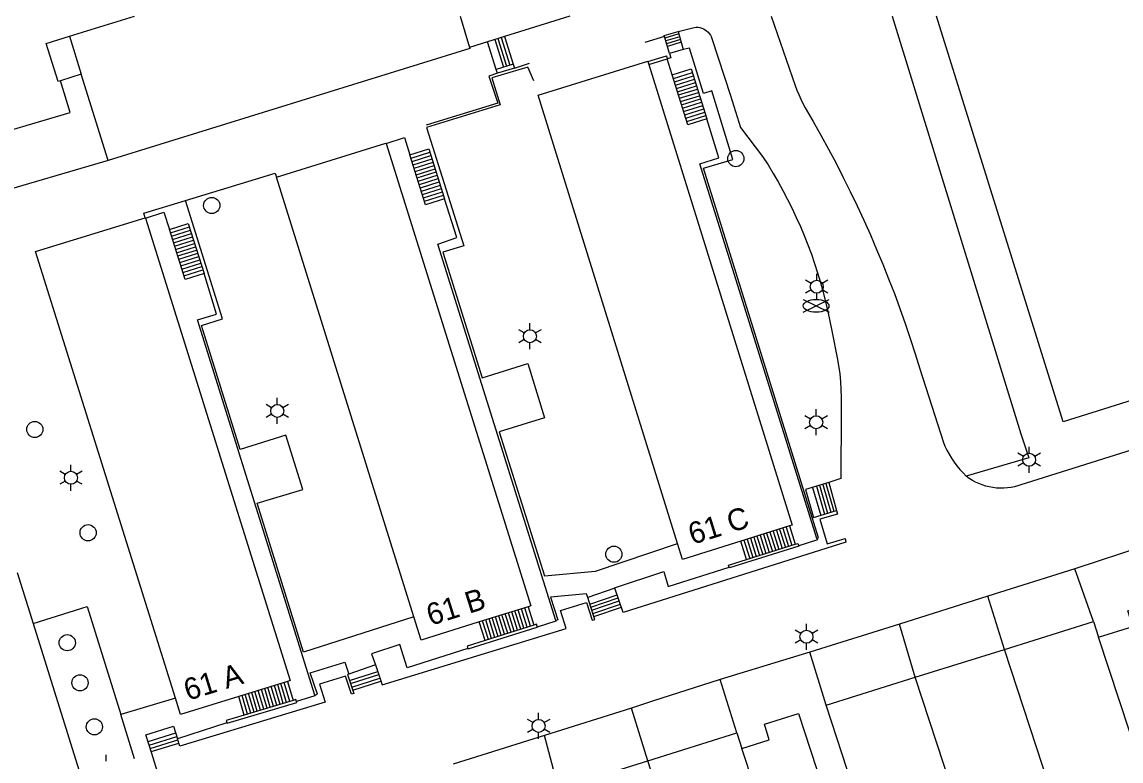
# Model space of a CAD drawing. Extents: x 122462 to 123306, y 485548 to 486417.
# Drawn here: x 122701.5 to 122777.6, y 486198.4 to 486249.6 of the extents above; entities that cross this region are included whole.
import ezdxf

# ---------------------------------------------------------------- set-up
doc = ezdxf.new("R2010")
doc.units = 0
for name, color, linetype in [('B-WE-IE-MEUBILAIR_WEGMEUBILAIR_VERKEERSBORD-S', 7, 'Continuous'), ('Level 1', 7, 'Continuous'), ('Level 17', 7, 'Continuous'), ('Level 19', 7, 'Continuous'), ('Level 21', 7, 'Continuous'), ('Level 31', 7, 'Continuous'), ('Level 33', 7, 'Continuous'), ('Level 4', 7, 'Continuous'), ('Level 50', 7, 'Continuous'), ('Level 52', 7, 'Continuous'), ('Level 53', 7, 'Continuous'), ('N-WE-AL-T25', 7, 'Continuous')]:
    doc.layers.add(name, color=color, linetype=linetype)

msp = doc.modelspace()

# ---------------------------------------------------------------- linework, layer by layer
at = {"layer": 'Level 1'}
for p, q in [((122704.806, 486248.607), (122709.3, 486250)), ((122739.426, 486250), (122734.916, 486248.585)), ((122734.916, 486248.585), (122733.743, 486248.217)), ((122733.743, 486248.217), (122732.497, 486247.826)), ((122744.836, 486246.849), (122744.901, 486246.641)), ((122728.649, 486208.4), (122719.125, 486238.839)), ((122710.053, 486236.037), (122710.064, 486236.01)), ((122754.637, 486214.699), (122751.263, 486213.648)), ((122780.735, 486213.823), (122774.385, 486211.733)), ((122701.191, 486211.491), (122702.294, 486207.955)), ((122774.385, 486211.733), (122768.357, 486209.846)), ((122768.357, 486209.846), (122762.257, 486207.893)), ((122736.54, 486209.108), (122733.171, 486208.054)), ((122769.508, 486206.159), (122775.679, 486208.086)), ((122775.679, 486208.086), (122776.018, 486207)), ((122702.294, 486207.955), (122706.11, 486195.719)), ((122762.257, 486207.893), (122756.038, 486205.965)), ((122756.038, 486205.965), (122749.842, 486204.065)), ((122763.336, 486204.232), (122769.508, 486206.159)), ((122757.165, 486202.305), (122763.336, 486204.232)), ((122719.89, 486203.937), (122716.522, 486202.896)), ((122743.708, 486202.097), (122737.689, 486200.198)), ((122760.501, 486192.189), (122757.165, 486202.305)), ((122737.689, 486200.198), (122731.364, 486198.223)), ((122744.822, 486198.451), (122750.993, 486200.378)), ((122750.993, 486200.378), (122751.331, 486199.294)), ((122738.65, 486196.524), (122744.822, 486198.451))]:
    msp.add_line(p, q, dxfattribs=at)
for points in [[(122780.782, 486224.161), (122773.57, 486221.91), (122764.823, 486250)], [(122704.175, 486245.515), (122704.015, 486245.466), (122703.196, 486248.108), (122704.806, 486248.607)], [(122732.497, 486247.826), (122732.509, 486247.762), (122721.776, 486244.438), (122707.472, 486240.007)], [(122746.894, 486213.482), (122737.25, 486244.529), (122744.826, 486246.877), (122744.836, 486246.849)], [(122744.901, 486246.641), (122754.828, 486214.758), (122754.637, 486214.699)], [(122698.105, 486241.345), (122704.857, 486243.315), (122704.175, 486245.515)], [(122719.125, 486238.839), (122722.916, 486240.025), (122726.706, 486241.211), (122726.715, 486241.182)], [(122726.715, 486241.182), (122736.73, 486209.167), (122736.54, 486209.108)], [(122707.472, 486240.007), (122699.259, 486237.61), (122699.226, 486237.726)], [(122712.133, 486202.784), (122702.462, 486233.692), (122710.053, 486236.037)], [(122710.064, 486236.01), (122720.079, 486203.995), (122719.89, 486203.937)], [(122751.263, 486213.648), (122747.231, 486212.391), (122746.894, 486213.482)], [(122776.018, 486207), (122778.405, 486207.745), (122778.066, 486208.831), (122781.851, 486210.013)], [(122733.171, 486208.054), (122729.15, 486206.795), (122728.649, 486208.4)], [(122749.842, 486204.065), (122745.162, 486202.563), (122743.708, 486202.097)], [(122716.522, 486202.896), (122712.488, 486201.65), (122712.133, 486202.784)], [(122751.331, 486199.294), (122753.241, 486199.89), (122752.903, 486200.974), (122755.256, 486201.709), (122757.349, 486195.363), (122756.4, 486195.05), (122757.497, 486191.726), (122757.179, 486191.095), (122754.363, 486190.167)]]:
    msp.add_lwpolyline(points, dxfattribs=at)
at = {"layer": 'Level 17'}
for p, q in [((122745.986, 486248.586), (122744.621, 486248.168)), ((122744.901, 486246.641), (122746.181, 486247.04)), ((122746.526, 486245.927), (122746.181, 486247.04)), ((122734.428, 486246.034), (122734.348, 486246.288)), ((122735.601, 486246.402), (122734.428, 486246.034)), ((122735.521, 486246.657), (122735.601, 486246.402)), ((122735.601, 486246.402), (122736.644, 486246.729)), ((122742.549, 486210.39), (122740.675, 486209.741)), ((122725.982, 486205.088), (122724.136, 486204.451)), ((122712.133, 486202.784), (122708.351, 486201.643)), ((122709.305, 486198.576), (122708.351, 486201.643)), ((122715.707, 486201.077), (122712.285, 486199.973))]:
    msp.add_line(p, q, dxfattribs=at)
for points in [[(122753.367, 486250), (122755.04, 486245.19), (122755.155, 486244.874), (122755.282, 486244.562), (122755.418, 486244.255), (122755.565, 486243.952), (122755.722, 486243.655), (122756.275, 486242.705), (122756.815, 486241.747), (122757.343, 486240.782), (122757.857, 486239.81), (122758.359, 486238.832), (122758.847, 486237.847), (122759.323, 486236.855), (122759.785, 486235.858), (122760.234, 486234.854), (122760.669, 486233.844), (122761.091, 486232.829), (122761.499, 486231.808), (122761.894, 486230.782), (122762.275, 486229.75), (122762.643, 486228.714), (122762.996, 486227.673), (122763.336, 486226.627), (122763.662, 486225.577), (122765.294, 486220.475), (122765.383, 486220.235), (122765.527, 486219.945), (122765.683, 486219.662), (122765.853, 486219.386), (122766.034, 486219.118), (122766.228, 486218.859), (122766.433, 486218.608), (122766.65, 486218.368), (122766.877, 486218.137)], [(122761.733, 486250), (122761.733, 486249.999), (122770.655, 486221.09), (122771.193, 486219.422), (122766.877, 486218.137)], [(122746.93, 486248.939), (122748.045, 486249.217), (122748.175, 486249.227), (122748.306, 486249.222), (122748.435, 486249.202), (122748.561, 486249.167), (122748.682, 486249.118), (122748.797, 486249.055), (122748.904, 486248.98), (122749.001, 486248.892), (122749.088, 486248.795), (122749.163, 486248.687), (122749.225, 486248.572), (122749.273, 486248.451), (122750.559, 486244.51), (122751.258, 486242.285), (122752.78, 486240.277), (122753.151, 486239.697), (122753.509, 486239.11), (122753.855, 486238.515), (122754.188, 486237.913), (122754.508, 486237.303), (122754.815, 486236.687), (122755.109, 486236.065), (122755.39, 486235.437), (122755.657, 486234.802), (122755.91, 486234.163), (122756.15, 486233.517), (122756.376, 486232.867), (122756.587, 486232.213), (122756.785, 486231.554), (122756.969, 486230.89), (122757.139, 486230.223), (122757.294, 486229.553), (122757.435, 486228.879), (122757.562, 486228.203), (122757.949, 486226.217), (122758.113, 486225.229), (122758.159, 486224.691), (122758.191, 486224.153), (122758.21, 486223.614), (122758.215, 486223.074), (122758.207, 486222.535), (122758.201, 486217.978), (122757.36, 486217.7), (122755.754, 486217.236), (122756.309, 486215.281), (122757.899, 486215.772), (122757.969, 486215.528), (122756.737, 486215.18), (122757.251, 486213.463), (122758.493, 486213.824), (122758.548, 486213.591), (122743.137, 486208.722), (122742.549, 486210.39)], [(122756.538, 486213.842), (122756.652, 486213.878), (122748.696, 486239.466), (122750.725, 486240.06), (122749.252, 486244.811), (122748.676, 486244.632), (122747.711, 486247.78), (122747.29, 486247.69)], [(122746.328, 486247.4), (122746.417, 486247.114), (122746.181, 486247.04)], [(122736.951, 486245.512), (122736.523, 486246.468), (122734.037, 486245.716), (122734.617, 486243.844), (122729.522, 486242.274), (122732.09, 486234.097), (122730.652, 486233.654), (122733.372, 486224.966), (122736.528, 486225.941), (122737.69, 486222.197), (122734.535, 486221.218), (122737.673, 486211.238), (122741.206, 486211.567), (122746.894, 486213.482)], [(122734.428, 486246.034), (122733.836, 486245.848), (122734.441, 486243.969), (122729.484, 486242.449)], [(122756.538, 486213.842), (122748.436, 486239.762), (122749.749, 486240.186), (122748.914, 486242.882)], [(122726.715, 486241.182), (122727.999, 486241.584), (122728.371, 486240.393)], [(122712.843, 486237.227), (122719.038, 486239.125), (122719.125, 486238.839)], [(122710.053, 486236.037), (122709.96, 486236.344), (122712.843, 486237.227)], [(122728.649, 486208.4), (122721, 486205.963), (122717.794, 486216.269), (122720.962, 486217.226), (122719.781, 486220.978), (122716.621, 486219.995), (122713.944, 486228.582), (122715.393, 486229.029), (122712.843, 486237.227)], [(122738.459, 486208.165), (122730.306, 486234.208), (122731.617, 486234.671), (122730.771, 486237.352)], [(122710.064, 486236.01), (122711.347, 486236.412), (122711.72, 486235.221)], [(122721.777, 486202.994), (122713.672, 486228.961), (122714.985, 486229.373), (122714.119, 486232.18)], [(122794.647, 486225.097), (122770.22, 486217.41), (122769.972, 486217.363), (122769.722, 486217.331), (122769.471, 486217.314), (122769.218, 486217.314), (122768.967, 486217.329), (122768.716, 486217.359), (122768.468, 486217.405), (122768.224, 486217.466), (122767.983, 486217.542), (122767.748, 486217.633), (122767.519, 486217.739), (122767.297, 486217.858), (122767.083, 486217.991), (122766.877, 486218.137)], [(122756.538, 486213.842), (122756.571, 486213.736), (122755.273, 486213.329)], [(122742.549, 486210.39), (122742.538, 486210.422), (122745.932, 486211.549), (122746.251, 486210.5), (122750.464, 486211.854)], [(122725.982, 486205.088), (122726.447, 486203.699), (122739.174, 486207.603), (122738.782, 486208.846), (122740.581, 486209.395), (122740.978, 486208.171), (122741.169, 486208.222), (122741.094, 486208.444), (122740.877, 486209.09), (122740.675, 486209.741)], [(122740.675, 486209.741), (122740.596, 486209.996), (122738.102, 486209.765), (122738.598, 486208.209), (122738.459, 486208.165)], [(122702.294, 486207.955), (122706.026, 486209.12), (122708.351, 486201.643)], [(122738.459, 486208.165), (122738.476, 486208.111), (122737.181, 486207.704)], [(122732.382, 486206.227), (122728.173, 486204.881), (122727.668, 486206.49), (122725.711, 486205.859), (122725.982, 486205.088)], [(122721.777, 486202.994), (122721.967, 486203.06), (122721.468, 486204.528), (122723.865, 486205.268), (122724.136, 486204.451)], [(122724.136, 486204.451), (122724.054, 486204.423), (122724.481, 486203.099), (122724.315, 486203.047), (122723.92, 486204.295), (122722.103, 486203.759), (122722.508, 486202.5), (122712.453, 486199.448), (122712.285, 486199.973)], [(122721.777, 486202.994), (122721.79, 486202.953), (122720.518, 486202.559)], [(122713.74, 486192.745), (122713.421, 486192.643), (122712.875, 486194.383), (122718.945, 486196.153), (122718.874, 486196.31), (122711.969, 486194.245), (122710.502, 486198.949), (122710.098, 486200.244), (122712.007, 486200.847), (122712.285, 486199.973)]]:
    msp.add_lwpolyline(points, dxfattribs=at)
at = {"layer": 'Level 19'}
for p, q in [((122778.917, 486198.257), (122776.018, 486207)), ((122772.778, 486196.235), (122769.508, 486206.159)), ((122766.64, 486194.212), (122763.336, 486204.232)), ((122754.363, 486190.167), (122751.331, 486199.294)), ((122748.225, 486188.145), (122744.822, 486198.451))]:
    msp.add_line(p, q, dxfattribs=at)
msp.add_lwpolyline([(122744.836, 486246.849), (122746.117, 486247.246), (122746.181, 486247.04)], dxfattribs=at)
at = {"layer": 'Level 21'}
for p, q in [((122751.663, 486212.375), (122755.032, 486213.431)), ((122736.937, 486207.837), (122733.571, 486206.78)), ((122720.281, 486202.621), (122716.903, 486201.613))]:
    msp.add_line(p, q, dxfattribs=at)
for points in [[(122755.032, 486213.431), (122755.222, 486213.491), (122755.24, 486213.435), (122755.273, 486213.329)], [(122755.273, 486213.329), (122755.282, 486213.3), (122750.483, 486211.795), (122750.464, 486211.854)], [(122750.464, 486211.854), (122750.423, 486211.986), (122751.663, 486212.375)], [(122732.382, 486206.227), (122732.391, 486206.2), (122737.181, 486207.704)], [(122737.181, 486207.704), (122737.164, 486207.758), (122737.121, 486207.895), (122736.937, 486207.837)], [(122733.571, 486206.78), (122732.331, 486206.391), (122732.382, 486206.227)], [(122715.707, 486201.077), (122715.715, 486201.049), (122720.539, 486202.489), (122720.518, 486202.559)], [(122720.518, 486202.559), (122720.482, 486202.681), (122720.281, 486202.621)], [(122716.903, 486201.613), (122715.658, 486201.241), (122715.707, 486201.077)]]:
    msp.add_lwpolyline(points, dxfattribs=at)
at = {"layer": 'Level 31'}
for p, q in [((122734.916, 486248.585), (122735.521, 486246.657)), ((122746.328, 486247.4), (122745.986, 486248.586)), ((122746.93, 486248.939), (122747.29, 486247.69)), ((122734.348, 486246.288), (122733.743, 486248.217)), ((122747.29, 486247.69), (122746.328, 486247.4)), ((122735.521, 486246.657), (122734.348, 486246.288)), ((122754.637, 486214.699), (122755.032, 486213.431)), ((122751.663, 486212.375), (122751.263, 486213.648)), ((122736.54, 486209.108), (122736.937, 486207.837)), ((122733.571, 486206.78), (122733.171, 486208.054)), ((122719.89, 486203.937), (122720.281, 486202.621)), ((122716.903, 486201.613), (122716.522, 486202.896))]:
    msp.add_line(p, q, dxfattribs=at)
for points in [[(122745.986, 486248.586), (122745.965, 486248.659), (122746.93, 486248.939)], [(122746.526, 486245.927), (122747.844, 486246.337), (122748.914, 486242.882)], [(122748.914, 486242.882), (122747.596, 486242.472), (122746.526, 486245.927)], [(122728.371, 486240.393), (122729.681, 486240.806), (122730.771, 486237.352)], [(122730.771, 486237.352), (122729.453, 486236.936), (122728.371, 486240.393)], [(122711.72, 486235.221), (122713.029, 486235.634), (122714.119, 486232.18)], [(122714.119, 486232.18), (122712.801, 486231.764), (122711.72, 486235.221)]]:
    msp.add_lwpolyline(points, dxfattribs=at)
at = {"layer": 'Level 33'}
for p, q in [((122734.236, 486248.371), (122734.838, 486246.453)), ((122734.457, 486248.441), (122735.057, 486246.53)), ((122734.688, 486248.513), (122735.288, 486246.601)), ((122746.983, 486248.757), (122746.02, 486248.467)), ((122747.038, 486248.565), (122746.076, 486248.275)), ((122747.094, 486248.372), (122746.131, 486248.082)), ((122747.149, 486248.18), (122746.187, 486247.89)), ((122746.602, 486245.682), (122747.915, 486246.09)), ((122746.673, 486245.452), (122747.986, 486245.861)), ((122746.744, 486245.223), (122748.058, 486245.632)), ((122746.815, 486244.994), (122748.133, 486245.404)), ((122746.886, 486244.764), (122748.204, 486245.175)), ((122746.957, 486244.535), (122748.275, 486244.945)), ((122747.028, 486244.306), (122748.346, 486244.716)), ((122747.099, 486244.077), (122748.417, 486244.487)), ((122747.17, 486243.848), (122748.488, 486244.258)), ((122747.241, 486243.618), (122748.559, 486244.029)), ((122747.312, 486243.388), (122748.63, 486243.799)), ((122747.383, 486243.159), (122748.701, 486243.57)), ((122747.454, 486242.93), (122748.772, 486243.34)), ((122747.525, 486242.701), (122748.843, 486243.111)), ((122728.443, 486240.164), (122729.753, 486240.577)), ((122728.515, 486239.935), (122729.825, 486240.348)), ((122728.586, 486239.705), (122729.898, 486240.119)), ((122728.658, 486239.476), (122729.97, 486239.891)), ((122728.73, 486239.247), (122730.042, 486239.662)), ((122728.801, 486239.018), (122730.114, 486239.433)), ((122728.877, 486238.791), (122730.187, 486239.204)), ((122728.949, 486238.562), (122730.259, 486238.975)), ((122729.021, 486238.333), (122730.331, 486238.746)), ((122729.094, 486238.104), (122730.403, 486238.517)), ((122729.166, 486237.875), (122730.476, 486238.288)), ((122729.238, 486237.646), (122730.548, 486238.06)), ((122729.31, 486237.417), (122730.62, 486237.831)), ((122729.382, 486237.188), (122730.692, 486237.602)), ((122711.791, 486234.992), (122713.102, 486235.405)), ((122711.863, 486234.763), (122713.174, 486235.176)), ((122711.935, 486234.534), (122713.246, 486234.947)), ((122712.006, 486234.304), (122713.318, 486234.718)), ((122712.078, 486234.075), (122713.391, 486234.49)), ((122712.15, 486233.846), (122713.463, 486234.261)), ((122712.221, 486233.617), (122713.535, 486234.032)), ((122712.298, 486233.39), (122713.607, 486233.803)), ((122712.37, 486233.161), (122713.679, 486233.574)), ((122712.442, 486232.932), (122713.752, 486233.345)), ((122712.514, 486232.703), (122713.824, 486233.116)), ((122712.586, 486232.474), (122713.896, 486232.887)), ((122712.659, 486232.245), (122713.968, 486232.659)), ((122712.731, 486232.016), (122714.041, 486232.43)), ((122756.234, 486217.375), (122756.796, 486215.431)), ((122756.501, 486217.452), (122757.061, 486215.513)), ((122756.719, 486217.515), (122757.278, 486215.58)), ((122756.938, 486217.578), (122757.495, 486215.647)), ((122757.157, 486217.641), (122757.713, 486215.715)), ((122757.36, 486217.7), (122757.899, 486215.772)), ((122752.833, 486214.137), (122753.232, 486212.867)), ((122753.057, 486214.207), (122753.456, 486212.937)), ((122753.283, 486214.277), (122753.681, 486213.008)), ((122753.507, 486214.347), (122753.905, 486213.078)), ((122753.731, 486214.416), (122754.129, 486213.148)), ((122753.955, 486214.486), (122754.353, 486213.219)), ((122754.179, 486214.556), (122754.577, 486213.289)), ((122754.404, 486214.626), (122754.802, 486213.359)), ((122751.487, 486213.718), (122751.887, 486212.445)), ((122751.711, 486213.788), (122752.111, 486212.515)), ((122751.935, 486213.857), (122752.335, 486212.586)), ((122752.16, 486213.928), (122752.56, 486212.656)), ((122752.385, 486213.997), (122752.784, 486212.726)), ((122752.609, 486214.067), (122753.008, 486212.797)), ((122740.808, 486209.294), (122742.71, 486209.934)), ((122740.88, 486209.081), (122742.784, 486209.722)), ((122736.037, 486207.554), (122735.637, 486208.828)), ((122736.261, 486207.624), (122735.861, 486208.898)), ((122736.486, 486207.695), (122736.086, 486208.969)), ((122736.71, 486207.765), (122736.31, 486209.039)), ((122740.951, 486208.868), (122742.859, 486209.51)), ((122741.025, 486208.651), (122742.935, 486209.294)), ((122741.094, 486208.444), (122743.008, 486209.089)), ((122733.795, 486206.85), (122733.395, 486208.124)), ((122734.019, 486206.92), (122733.619, 486208.194)), ((122734.243, 486206.991), (122733.843, 486208.265)), ((122734.468, 486207.061), (122734.068, 486208.335)), ((122734.692, 486207.132), (122734.292, 486208.406)), ((122734.916, 486207.202), (122734.516, 486208.476)), ((122735.14, 486207.272), (122734.74, 486208.546)), ((122735.364, 486207.343), (122734.964, 486208.617)), ((122735.589, 486207.413), (122735.189, 486208.687)), ((122735.813, 486207.484), (122735.413, 486208.758)), ((122724.187, 486204.01), (122726.136, 486204.638)), ((122724.257, 486203.792), (122726.208, 486204.421)), ((122718.704, 486202.15), (122718.318, 486203.451)), ((122718.929, 486202.217), (122718.542, 486203.52)), ((122719.154, 486202.285), (122718.767, 486203.59)), ((122719.38, 486202.352), (122718.992, 486203.659)), ((122719.605, 486202.419), (122719.216, 486203.728)), ((122719.83, 486202.486), (122719.441, 486203.798)), ((122720.056, 486202.554), (122719.666, 486203.867)), ((122724.338, 486203.544), (122726.29, 486204.174)), ((122724.407, 486203.328), (122726.361, 486203.958)), ((122717.128, 486201.68), (122716.746, 486202.965)), ((122717.353, 486201.747), (122716.971, 486203.035)), ((122717.579, 486201.814), (122717.196, 486203.104)), ((122717.804, 486201.882), (122717.42, 486203.174)), ((122718.029, 486201.949), (122717.644, 486203.243)), ((122718.254, 486202.014), (122717.869, 486203.312)), ((122718.479, 486202.083), (122718.094, 486203.382)), ((122710.242, 486199.784), (122712.156, 486200.381)), ((122710.318, 486199.537), (122712.234, 486200.135)), ((122710.391, 486199.304), (122712.308, 486199.902)), ((122710.461, 486199.079), (122712.38, 486199.677))]:
    msp.add_line(p, q, dxfattribs=at)
at = {"layer": 'Level 4'}
for p, q in [((122704.806, 486248.607), (122705.625, 486245.965)), ((122705.625, 486245.965), (122704.175, 486245.515)), ((122775.679, 486208.086), (122774.385, 486211.733)), ((122769.508, 486206.159), (122768.357, 486209.846)), ((122763.336, 486204.232), (122762.257, 486207.893)), ((122757.165, 486202.305), (122756.038, 486205.965)), ((122750.993, 486200.378), (122749.842, 486204.065)), ((122744.822, 486198.451), (122743.708, 486202.097)), ((122738.65, 486196.524), (122737.689, 486200.198))]:
    msp.add_line(p, q, dxfattribs=at)
at = {"layer": 'Level 50'}
for p, q in [((122756.13, 486231.49), (122755.74, 486231.715)), ((122756.52, 486231.715), (122756.52, 486232.165)), ((122757.299, 486231.715), (122756.909, 486231.49)), ((122756.13, 486231.04), (122755.74, 486230.815)), ((122757.299, 486230.815), (122756.909, 486231.04)), ((122756.52, 486230.365), (122756.52, 486230.815)), ((122736.675, 486228.285), (122736.675, 486228.735)), ((122736.285, 486228.06), (122735.895, 486228.285)), ((122737.454, 486228.285), (122737.064, 486228.06)), ((122736.285, 486227.61), (122735.895, 486227.385)), ((122736.675, 486226.935), (122736.675, 486227.385)), ((122737.454, 486227.385), (122737.064, 486227.61)), ((122719.188, 486223.114), (122719.188, 486223.564)), ((122718.798, 486222.889), (122718.408, 486223.114)), ((122719.967, 486223.114), (122719.577, 486222.889)), ((122756.484, 486222.326), (122756.484, 486222.776)), ((122718.798, 486222.439), (122718.408, 486222.214)), ((122719.188, 486221.764), (122719.188, 486222.214)), ((122719.967, 486222.214), (122719.577, 486222.439)), ((122756.094, 486222.101), (122755.704, 486222.326)), ((122757.263, 486222.326), (122756.873, 486222.101)), ((122756.094, 486221.651), (122755.704, 486221.426)), ((122756.484, 486220.976), (122756.484, 486221.426)), ((122757.263, 486221.426), (122756.873, 486221.651)), ((122771.225, 486219.738), (122771.225, 486220.188)), ((122770.835, 486219.513), (122770.445, 486219.738)), ((122772.004, 486219.738), (122771.614, 486219.513)), ((122704.907, 486218.484), (122704.907, 486218.934)), ((122770.835, 486219.063), (122770.445, 486218.838)), ((122771.225, 486218.388), (122771.225, 486218.838)), ((122772.004, 486218.838), (122771.614, 486219.063)), ((122704.517, 486218.259), (122704.127, 486218.484)), ((122705.686, 486218.484), (122705.296, 486218.259)), ((122704.517, 486217.809), (122704.127, 486217.584)), ((122704.907, 486217.134), (122704.907, 486217.584)), ((122705.686, 486217.584), (122705.296, 486217.809)), ((122755.423, 486207.262), (122755.033, 486207.487)), ((122755.813, 486207.487), (122755.813, 486207.937)), ((122756.592, 486207.487), (122756.202, 486207.262)), ((122755.423, 486206.812), (122755.033, 486206.587)), ((122755.813, 486206.137), (122755.813, 486206.587)), ((122756.592, 486206.587), (122756.202, 486206.812)), ((122736.886, 486201.088), (122736.496, 486201.313)), ((122737.276, 486201.313), (122737.276, 486201.763)), ((122738.055, 486201.313), (122737.665, 486201.088)), ((122736.886, 486200.638), (122736.496, 486200.413)), ((122737.276, 486199.963), (122737.276, 486200.413)), ((122738.055, 486200.413), (122737.665, 486200.638)), ((122707.353, 486198.409), (122707.353, 486198.859))]:
    msp.add_line(p, q, dxfattribs=at)
for centre in [(122756.52, 486231.265), (122736.675, 486227.835), (122719.188, 486222.664), (122756.484, 486221.876), (122771.225, 486219.288), (122704.907, 486218.034), (122755.813, 486207.037), (122737.276, 486200.863)]:
    msp.add_circle(centre, 0.45, dxfattribs=at)
at = {"layer": 'Level 52'}
for p, q in [((122755.592, 486229.493), (122757.373, 486230.383)), ((122755.592, 486230.383), (122757.373, 486229.493))]:
    msp.add_line(p, q, dxfattribs=at)
msp.add_ellipse((122756.482, 486229.936), major_axis=(0.89, 0), ratio=0.5, dxfattribs=at)
at = {"layer": 'Level 53'}
for centre in [(122750.924, 486240.132), (122714.652, 486236.887), (122702.405, 486221.381), (122706.095, 486214.232), (122742.482, 486212.745), (122704.651, 486206.618), (122705.534, 486203.845), (122706.53, 486200.796)]:
    msp.add_circle(centre, 0.56, dxfattribs=at)
at = {"layer": 'N-WE-AL-T25'}
for p, q in [((122731.842, 486250), (122732.497, 486247.826)), ((122707.472, 486240.007), (122705.625, 486245.965))]:
    msp.add_line(p, q, dxfattribs=at)

# ---------------------------------------------------------------- texts
at = {"layer": 'B-WE-IE-MEUBILAIR_WEGMEUBILAIR_VERKEERSBORD-S'}
for s, rotation, p in [('61 C', 17.29258, (122747.918, 486213.392)), ('61 B', 17.38597, (122729.797, 486207.784)), ('61 A', 17.17265, (122712.997, 486202.592))]:
    msp.add_text(s, height=1.5, rotation=rotation, dxfattribs=at).set_placement(p)

doc.saveas('drawing.dxf')
